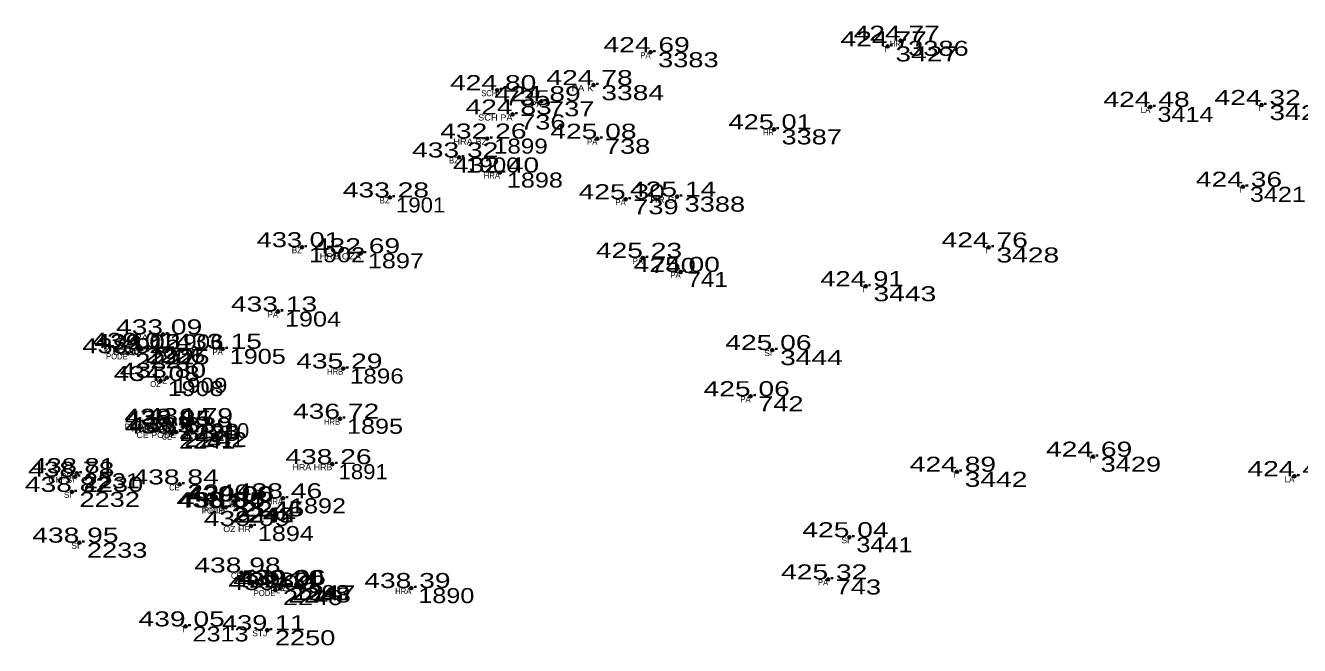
# Model space of a CAD drawing. Extents: x -639390 to -639074, y -1138747 to -1138358.
# Drawn here: x -639327.8 to -639264.4, y -1138469.3 to -1138438.4 of the extents above; entities that cross this region are included whole.
import ezdxf
from ezdxf.enums import TextEntityAlignment as Align

# ---------------------------------------------------------------- set-up
doc = ezdxf.new("R2010")
doc.units = 0
doc.header["$LTSCALE"] = 0.3
doc.header["$PDMODE"] = 32
doc.header["$PDSIZE"] = 0.15
for name, color, linetype in [('11', 7, 'Continuous'), ('12', 7, 'Continuous'), ('13', 7, 'Continuous'), ('57', 7, 'Continuous')]:
    doc.layers.add(name, color=color, linetype=linetype)

msp = doc.modelspace()

# ---------------------------------------------------------------- linework, layer by layer
at = {"layer": '11'}
for p in [(-639284.88, -1138439.43), (-639284.23, -1138439.15), (-639296.68, -1138439.72), (-639299.52, -1138441.36), (-639304.32, -1138441.61), (-639302.11, -1138442.16), (-639271.79, -1138442.44), (-639266.26, -1138442.35), (-639303.55, -1138442.82), (-639304.81, -1138444.02), (-639299.33, -1138444.03), (-639290.54, -1138443.56), (-639306.21, -1138444.96), (-639304.18, -1138445.71), (-639267.19, -1138446.42), (-639309.66, -1138446.95), (-639297.92, -1138447.04), (-639295.36, -1138446.91), (-639314.03, -1138449.43), (-639311.1, -1138449.73), (-639279.85, -1138449.44), (-639297.06, -1138449.96), (-639295.18, -1138450.66), (-639285.97, -1138451.37), (-639315.23, -1138452.63), (-639320.95, -1138453.77), (-639322.71, -1138454.71), (-639322.23, -1138454.44), (-639322.03, -1138454.51), (-639322.02, -1138454.5), (-639317.98, -1138454.49), (-639290.62, -1138454.55), (-639311.98, -1138455.47), (-639321.07, -1138456.09), (-639320.76, -1138455.93), (-639291.7, -1138456.85), (-639312.14, -1138457.97), (-639320.54, -1138458.22), (-639320.5, -1138458.32), (-639320.29, -1138458.63), (-639319.42, -1138458.19), (-639320.5, -1138458.71), (-639319.46, -1138458.65), (-639274.65, -1138459.86), (-639312.52, -1138460.23), (-639325.33, -1138460.86), (-639325.24, -1138460.68), (-639281.43, -1138460.61), (-639264.62, -1138460.83), (-639325.49, -1138461.61), (-639320.13, -1138461.24), (-639317.94, -1138462.39), (-639317.83, -1138462.38), (-639317.44, -1138462.08), (-639317.37, -1138462.09), (-639314.98, -1138461.93), (-639316.58, -1138463.31), (-639325.12, -1138464.14), (-639286.78, -1138463.87), (-639317.05, -1138465.63), (-639314.8, -1138466.25), (-639287.84, -1138465.97), (-639315.36, -1138466.5), (-639315.11, -1138466.37), (-639314.89, -1138466.26), (-639308.59, -1138466.4), (-639319.83, -1138468.31), (-639315.76, -1138468.5)]:
    msp.add_point(p, dxfattribs=at)

# ---------------------------------------------------------------- texts
at = {"layer": '12'}
for s, width, p in [('424.77 ', 1.4, (-639284.88, -1138439.43)), ('424.77 ', 1.4, (-639284.23, -1138439.15)), ('424.69 ', 1.4, (-639296.68, -1138439.72)), ('424.78 ', 1.4, (-639299.52, -1138441.36)), ('424.80 ', 1.4, (-639304.32, -1138441.61)), ('424.89 ', 1.4, (-639302.11, -1138442.16)), ('424.83 ', 1.4, (-639303.55, -1138442.82)), ('424.48 ', 1.4, (-639271.79, -1138442.44)), ('424.32 ', 1.4, (-639266.26, -1138442.35)), ('432.26 ', 1.4, (-639304.809, -1138444.02)), ('425.08 ', 1.4, (-639299.33, -1138444.03)), ('425.01 ', 1.35, (-639290.539, -1138443.56)), ('433.32 ', 1.4, (-639306.21, -1138444.96)), ('432.40 ', 1.4, (-639304.18, -1138445.71)), ('424.36 ', 1.4, (-639267.189, -1138446.42)), ('433.28 ', 1.4, (-639309.66, -1138446.95)), ('425.30 ', 1.4, (-639297.92, -1138447.04)), ('425.14 ', 1.4, (-639295.36, -1138446.91)), ('433.01 ', 1.35, (-639314.029, -1138449.43)), ('432.69 ', 1.4, (-639311.1, -1138449.73)), ('424.76 ', 1.4, (-639279.849, -1138449.44)), ('425.23 ', 1.4, (-639297.06, -1138449.96)), ('425.00 ', 1.4, (-639295.18, -1138450.66)), ('424.91 ', 1.35, (-639285.969, -1138451.37)), ('433.13 ', 1.4, (-639315.23, -1138452.63)), ('433.09 ', 1.4, (-639320.95, -1138453.77)), ('438.91 ', 1.35, (-639322.709, -1138454.71)), ('439.01 ', 1.35, (-639322.229, -1138454.44)), ('439.02 ', 1.4, (-639322.03, -1138454.51)), ('434.15 ', 1.4, (-639322.02, -1138454.5)), ('433.15 ', 1.4, (-639317.98, -1138454.49)), ('425.06 ', 1.4, (-639290.619, -1138454.55)), ('435.29 ', 1.4, (-639311.98, -1138455.47)), ('434.08 ', 1.4, (-639321.07, -1138456.09)), ('433.80 ', 1.4, (-639320.76, -1138455.93)), ('425.06 ', 1.4, (-639291.699, -1138456.85)), ('436.72 ', 1.4, (-639312.14, -1138457.97)), ('438.94 ', 1.4, (-639320.54, -1138458.22)), ('438.85 ', 1.4, (-639320.5, -1138458.32)), ('438.83 ', 1.4, (-639320.29, -1138458.63)), ('435.39 ', 1.4, (-639319.46, -1138458.65)), ('434.79 ', 1.4, (-639319.42, -1138458.19)), ('438.77 ', 1.4, (-639320.5, -1138458.71)), ('424.69 ', 1.4, (-639274.65, -1138459.86)), ('438.26 ', 1.4, (-639312.519, -1138460.23)), ('438.78 ', 1.4, (-639325.33, -1138460.86)), ('438.81 ', 1.35, (-639325.239, -1138460.68)), ('424.89 ', 1.4, (-639281.43, -1138460.61)), ('424.43 ', 1.4, (-639264.62, -1138460.83)), ('438.82 ', 1.4, (-639325.49, -1138461.61)), ('438.84 ', 1.4, (-639320.13, -1138461.24)), ('438.84 ', 1.4, (-639317.94, -1138462.39)), ('438.85 ', 1.4, (-639317.83, -1138462.38)), ('439.00 ', 1.4, (-639317.44, -1138462.08)), ('439.06 ', 1.4, (-639317.369, -1138462.09)), ('438.46 ', 1.4, (-639314.979, -1138461.93)), ('439.09 ', 1.4, (-639316.58, -1138463.31)), ('438.95 ', 1.4, (-639325.12, -1138464.14)), ('425.04 ', 1.4, (-639286.78, -1138463.87)), ('438.98 ', 1.4, (-639317.05, -1138465.63)), ('439.20 ', 1.4, (-639314.89, -1138466.26)), ('439.06 ', 1.4, (-639314.799, -1138466.25)), ('425.32 ', 1.4, (-639287.84, -1138465.97)), ('439.09 ', 1.4, (-639315.36, -1138466.5)), ('439.14 ', 1.4, (-639315.11, -1138466.37)), ('438.39 ', 1.4, (-639308.59, -1138466.4)), ('439.05 ', 1.4, (-639319.83, -1138468.31)), ('439.11 ', 1.35, (-639315.759, -1138468.5))]:
    msp.add_text(s, height=0.75, dxfattribs=dict(at, width=width)).set_placement(p, align=Align.CENTER)
at = {"layer": '13'}
for s, width, p in [(' 3427', 1.4, (-639284.88, -1138440.18)), (' 3386', 1.35, (-639284.23, -1138439.9)), (' 3383', 1.35, (-639296.68, -1138440.47)), (' 3384', 1.4, (-639299.52, -1138442.11)), (' 735', 1.35, (-639304.32, -1138442.36)), (' 737', 1.35, (-639302.11, -1138442.91)), (' 3414', 1.25, (-639271.79, -1138443.19)), (' 3425', 1.4, (-639266.26, -1138443.1)), (' 736', 1.35, (-639303.55, -1138443.57)), (' 3387', 1.35, (-639290.54, -1138444.31)), (' 1899', 1.2, (-639304.81, -1138444.77)), (' 738', 1.35, (-639299.33, -1138444.78)), (' 1900', 1.2, (-639306.21, -1138445.71)), (' 1898', 1.25, (-639304.18, -1138446.46)), (' 3421', 1.25, (-639267.19, -1138447.17)), (' 1901', 1.1, (-639309.66, -1138447.7)), (' 739', 1.35, (-639297.92, -1138447.79)), (' 3388', 1.35, (-639295.36, -1138447.66)), (' 1902', 1.25, (-639314.03, -1138450.18)), (' 3428', 1.4, (-639279.85, -1138450.19)), (' 1897', 1.25, (-639311.1, -1138450.48)), (' 740', 1.35, (-639297.06, -1138450.71)), (' 741', 1.2, (-639295.18, -1138451.41)), (' 3443', 1.4, (-639285.97, -1138452.12)), (' 1904', 1.25, (-639315.23, -1138453.38)), (' 1906', 1.2, (-639320.95, -1138454.52)), (' 2227', 1.35, (-639322.71, -1138455.46)), (' 2226', 1.35, (-639322.23, -1138455.19)), (' 2225', 1.35, (-639322.03, -1138455.26)), (' 1907', 1.25, (-639322.02, -1138455.25)), (' 1905', 1.25, (-639317.98, -1138455.24)), (' 3444', 1.4, (-639290.62, -1138455.3)), (' 1909', 1.2, (-639320.76, -1138456.68)), (' 1896', 1.2, (-639311.98, -1138456.22)), (' 1908', 1.25, (-639321.07, -1138456.84)), (' 742', 1.35, (-639291.7, -1138457.6)), (' 2228', 1.35, (-639320.54, -1138458.97)), (' 2229', 1.35, (-639320.5, -1138459.07)), (' 1910', 1.1, (-639319.42, -1138458.94)), (' 1895', 1.25, (-639312.14, -1138458.72)), (' 2241', 1.25, (-639320.5, -1138459.46)), (' 2242', 1.4, (-639320.29, -1138459.38)), (' 1891', 1.1, (-639312.52, -1138460.98)), (' 3429', 1.35, (-639274.65, -1138460.61)), (' 2230', 1.35, (-639325.33, -1138461.61)), (' 2231', 1.25, (-639325.24, -1138461.43)), (' 3442', 1.4, (-639281.43, -1138461.36)), (' 2232', 1.35, (-639325.49, -1138462.36)), (' 2240', 1.4, (-639320.13, -1138461.99)), (' 2244', 1.4, (-639317.83, -1138463.13)), (' 2245', 1.4, (-639317.44, -1138462.83)), (' 2246', 1.35, (-639317.37, -1138462.84)), (' 1892', 1.25, (-639314.98, -1138462.68)), (' 2243', 1.4, (-639317.94, -1138463.14)), (' 1894', 1.25, (-639316.58, -1138464.06)), (' 2233', 1.35, (-639325.12, -1138464.89)), (' 3441', 1.25, (-639286.78, -1138464.62)), (' 2239', 1.35, (-639317.05, -1138466.38)), (' 743', 1.35, (-639287.84, -1138466.72)), (' 2249', 1.35, (-639315.36, -1138467.25)), (' 2248', 1.4, (-639315.11, -1138467.12)), (' 2247', 1.4, (-639314.89, -1138467.01)), (' 1893', 1.25, (-639314.8, -1138467)), (' 1890', 1.25, (-639308.59, -1138467.15)), (' 2313', 1.25, (-639319.83, -1138469.06)), (' 2250', 1.35, (-639315.76, -1138469.25))]:
    msp.add_text(s, height=0.75, dxfattribs=dict(at, width=width)).set_placement(p)
msp.add_text(' 1911', height=0.75, dxfattribs=at).set_placement((-639319.46, -1138459.4))
at = {"layer": '57'}
for s, width, p in [('T', 0.85, (-639284.88, -1138439.73)), ('HR', 0.85, (-639284.229, -1138439.45)), ('PA', 0.95, (-639296.68, -1138440.02)), ('PA K', 1.2, (-639299.519, -1138441.66)), ('SCH', 0.9, (-639304.319, -1138441.91)), ('PA', 0.95, (-639302.11, -1138442.46)), ('T', 0.85, (-639266.26, -1138442.65)), ('SCH PA', 1.15, (-639303.55, -1138443.12)), ('HR', 0.85, (-639290.539, -1138443.86)), ('HRA BZ', 1.15, (-639304.809, -1138444.32)), ('PA', 0.95, (-639299.33, -1138444.33)), ('HRA', 0.95, (-639304.18, -1138446.01)), ('T', 0.85, (-639267.19, -1138446.72)), ('PA', 0.95, (-639297.92, -1138447.34)), ('HR SI', 1.25, (-639295.36, -1138447.21)), ('T', 0.85, (-639279.85, -1138449.74)), ('HRB OZA', 1.15, (-639311.1, -1138450.03)), ('PA', 0.95, (-639297.06, -1138450.26)), ('PA', 0.95, (-639295.18, -1138450.96)), ('T', 0.85, (-639285.97, -1138451.67)), ('PA', 0.95, (-639315.23, -1138452.93)), ('PA BZ', 1.2, (-639320.949, -1138454.07)), ('K PODE', 1.1, (-639322.23, -1138454.74)), ('PODE', 0.95, (-639322.71, -1138455.01)), ('BZ OZ', 1.2, (-639322.019, -1138454.8)), ('PA', 0.95, (-639317.98, -1138454.79)), ('SI', 1.05, (-639290.62, -1138454.85)), ('OZ', 0.9, (-639320.759, -1138456.23)), ('HRB', 0.95, (-639311.979, -1138455.77)), ('OZ', 0.9, (-639321.069, -1138456.39)), ('PA', 0.95, (-639291.7, -1138457.15)), ('PODE OBR', 1.1, (-639320.539, -1138458.52)), ('PODE CH', 1.1, (-639320.499, -1138458.62)), ('OZ', 0.9, (-639319.419, -1138458.49)), ('HRB', 0.95, (-639312.139, -1138458.27)), ('CE PODE', 1.1, (-639320.29, -1138458.93)), ('CE', 0.9, (-639320.5, -1138459.01)), ('OZ', 0.9, (-639319.459, -1138458.95)), ('HRA HRB', 1.1, (-639312.519, -1138460.53)), ('T', 0.85, (-639274.65, -1138460.16)), ('CH SI', 1.25, (-639325.33, -1138461.16)), ('OBR', 0.9, (-639325.239, -1138460.98)), ('T', 0.85, (-639281.43, -1138460.91)), ('SI', 1.05, (-639325.49, -1138461.91)), ('CE', 0.9, (-639320.13, -1138461.54)), ('K', 0.65, (-639317.439, -1138462.38)), ('K', 0.65, (-639317.369, -1138462.39)), ('HRA', 0.95, (-639314.98, -1138462.23)), ('PODE', 0.95, (-639317.94, -1138462.69)), ('PODE', 0.95, (-639317.83, -1138462.68)), ('OZ HR', 1.1, (-639316.579, -1138463.61)), ('SI', 1.05, (-639325.12, -1138464.44)), ('SI', 1.05, (-639286.78, -1138464.17)), ('CE', 0.9, (-639317.05, -1138465.93)), ('PA', 0.95, (-639287.84, -1138466.27)), ('PODE', 0.95, (-639315.36, -1138466.8)), ('OZ', 0.9, (-639314.799, -1138466.55)), ('K', 0.65, (-639314.889, -1138466.56)), ('HRA', 0.95, (-639308.59, -1138466.7)), ('T', 0.85, (-639319.83, -1138468.61)), ('STJ', 1.05, (-639315.76, -1138468.8))]:
    msp.add_text(s, height=0.3, dxfattribs=dict(at, width=width)).set_placement(p, align=Align.RIGHT)
for s, p in [('LA', (-639271.79, -1138442.74)), ('BZ', (-639306.209, -1138445.26)), ('BZ', (-639309.659, -1138447.25)), ('BZ', (-639314.029, -1138449.73)), ('BZ', (-639322.029, -1138454.81)), ('LA', (-639264.62, -1138461.13)), ('PL', (-639315.109, -1138466.67))]:
    msp.add_text(s, height=0.3, dxfattribs=at).set_placement(p, align=Align.RIGHT)

doc.saveas('drawing.dxf')
